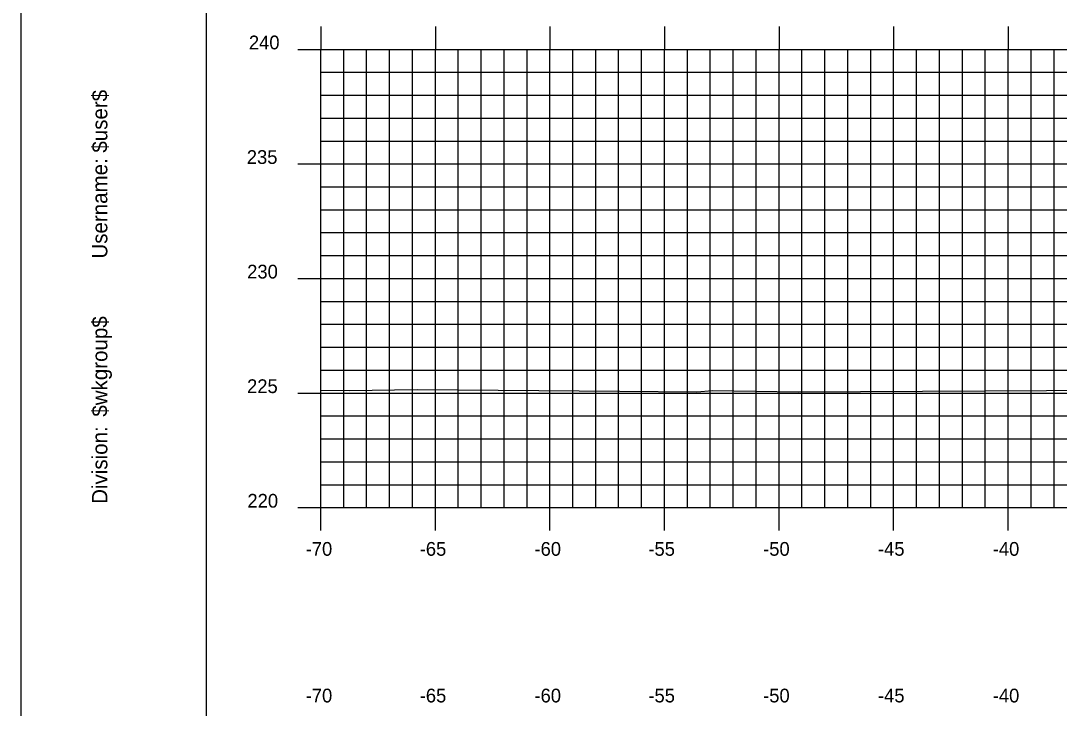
# Model space of a CAD drawing. Extents: x 1136989 to 1137159, y 608981 to 609091.
# Drawn here: x 1136989.05 to 1137034.37, y 609016.58 to 609046.58 of the extents above; entities that cross this region are included whole.
import ezdxf

# ---------------------------------------------------------------- set-up
doc = ezdxf.new("R2010")
doc.units = 0
for name, color, linetype in [('BORDER', 7, 'Continuous'), ('H_V ANNOTATION', 7, 'Continuous'), ('MAJOR', 7, 'Continuous'), ('MINOR', 7, 'Continuous'), ('PLOT BOUNDARY', 7, 'Continuous'), ('S_Roadway_Centerline', 7, 'Continuous')]:
    doc.layers.add(name, color=color, linetype=linetype)

msp = doc.modelspace()

# ---------------------------------------------------------------- linework, layer by layer
at = {"layer": 'BORDER'}
msp.add_lwpolyline([(1136997.14, 608984.335), (1137157.14, 608984.335), (1137157.14, 609089.335), (1136997.14, 609089.335)], close=True, dxfattribs=at)
at = {"layer": 'MAJOR'}
for p, q in [((1137002.14, 609046.337), (1137002.14, 609045.335)), ((1137007.14, 609046.337), (1137007.14, 609045.335)), ((1137012.14, 609046.337), (1137012.14, 609045.335)), ((1137017.14, 609046.337), (1137017.14, 609045.335)), ((1137022.14, 609046.337), (1137022.14, 609045.335)), ((1137027.14, 609046.337), (1137027.14, 609045.335)), ((1137032.14, 609046.337), (1137032.14, 609045.335)), ((1137001.138, 609045.335), (1137002.14, 609045.335)), ((1137002.14, 609045.335), (1137142.14, 609045.335)), ((1137002.14, 609025.335), (1137002.14, 609045.335)), ((1137002.14, 609025.335), (1137002.14, 609045.335)), ((1137002.14, 609045.335), (1137142.14, 609045.335)), ((1137007.14, 609025.335), (1137007.14, 609045.335)), ((1137012.14, 609025.335), (1137012.14, 609045.335)), ((1137017.14, 609025.335), (1137017.14, 609045.335)), ((1137022.14, 609025.335), (1137022.14, 609045.335)), ((1137027.14, 609025.335), (1137027.14, 609045.335)), ((1137032.14, 609025.335), (1137032.14, 609045.335)), ((1137001.138, 609040.335), (1137002.14, 609040.335)), ((1137002.14, 609040.335), (1137142.14, 609040.335)), ((1137001.138, 609035.335), (1137002.14, 609035.335)), ((1137002.14, 609035.335), (1137142.14, 609035.335)), ((1137001.138, 609030.335), (1137002.14, 609030.335)), ((1137002.14, 609030.335), (1137142.14, 609030.335)), ((1137001.138, 609025.335), (1137002.14, 609025.335)), ((1137002.14, 609025.335), (1137142.14, 609025.335)), ((1137002.14, 609025.335), (1137142.14, 609025.335)), ((1137002.14, 609024.333), (1137002.14, 609025.335)), ((1137007.14, 609024.333), (1137007.14, 609025.335)), ((1137012.14, 609024.333), (1137012.14, 609025.335)), ((1137017.14, 609024.333), (1137017.14, 609025.335)), ((1137022.14, 609024.333), (1137022.14, 609025.335)), ((1137027.14, 609024.333), (1137027.14, 609025.335)), ((1137032.14, 609024.333), (1137032.14, 609025.335))]:
    msp.add_line(p, q, dxfattribs=at)
at = {"layer": 'MINOR'}
for p, q in [((1137003.14, 609025.335), (1137003.14, 609045.335)), ((1137004.14, 609025.335), (1137004.14, 609045.335)), ((1137005.14, 609025.335), (1137005.14, 609045.335)), ((1137006.14, 609025.335), (1137006.14, 609045.335)), ((1137008.14, 609025.335), (1137008.14, 609045.335)), ((1137009.14, 609025.335), (1137009.14, 609045.335)), ((1137010.14, 609025.335), (1137010.14, 609045.335)), ((1137011.14, 609025.335), (1137011.14, 609045.335)), ((1137013.14, 609025.335), (1137013.14, 609045.335)), ((1137014.14, 609025.335), (1137014.14, 609045.335)), ((1137015.14, 609025.335), (1137015.14, 609045.335)), ((1137016.14, 609025.335), (1137016.14, 609045.335)), ((1137018.14, 609025.335), (1137018.14, 609045.335)), ((1137019.14, 609025.335), (1137019.14, 609045.335)), ((1137020.14, 609025.335), (1137020.14, 609045.335)), ((1137021.14, 609025.335), (1137021.14, 609045.335)), ((1137023.14, 609025.335), (1137023.14, 609045.335)), ((1137024.14, 609025.335), (1137024.14, 609045.335)), ((1137025.14, 609025.335), (1137025.14, 609045.335)), ((1137026.14, 609025.335), (1137026.14, 609045.335)), ((1137028.14, 609025.335), (1137028.14, 609045.335)), ((1137029.14, 609025.335), (1137029.14, 609045.335)), ((1137030.14, 609025.335), (1137030.14, 609045.335)), ((1137031.14, 609025.335), (1137031.14, 609045.335)), ((1137033.14, 609025.335), (1137033.14, 609045.335)), ((1137034.14, 609025.335), (1137034.14, 609045.335)), ((1137002.14, 609044.335), (1137142.14, 609044.335)), ((1137002.14, 609044.335), (1137003.142, 609044.335)), ((1137002.14, 609043.335), (1137142.14, 609043.335)), ((1137002.14, 609043.335), (1137003.142, 609043.335)), ((1137002.14, 609042.335), (1137142.14, 609042.335)), ((1137002.14, 609042.335), (1137003.142, 609042.335)), ((1137002.14, 609041.335), (1137142.14, 609041.335)), ((1137002.14, 609041.335), (1137003.142, 609041.335)), ((1137002.14, 609039.335), (1137142.14, 609039.335)), ((1137002.14, 609039.335), (1137003.142, 609039.335)), ((1137002.14, 609038.335), (1137142.14, 609038.335)), ((1137002.14, 609038.335), (1137003.142, 609038.335)), ((1137002.14, 609037.335), (1137142.14, 609037.335)), ((1137002.14, 609037.335), (1137003.142, 609037.335)), ((1137002.14, 609036.335), (1137142.14, 609036.335)), ((1137002.14, 609036.335), (1137003.142, 609036.335)), ((1137002.14, 609034.335), (1137142.14, 609034.335)), ((1137002.14, 609034.335), (1137003.142, 609034.335)), ((1137002.14, 609033.335), (1137142.14, 609033.335)), ((1137002.14, 609033.335), (1137003.142, 609033.335)), ((1137002.14, 609032.335), (1137142.14, 609032.335)), ((1137002.14, 609032.335), (1137003.142, 609032.335)), ((1137002.14, 609031.335), (1137142.14, 609031.335)), ((1137002.14, 609031.335), (1137003.142, 609031.335)), ((1137002.14, 609029.335), (1137142.14, 609029.335)), ((1137002.14, 609029.335), (1137003.142, 609029.335)), ((1137002.14, 609028.335), (1137142.14, 609028.335)), ((1137002.14, 609028.335), (1137003.142, 609028.335)), ((1137002.14, 609027.335), (1137142.14, 609027.335)), ((1137002.14, 609027.335), (1137003.142, 609027.335)), ((1137002.14, 609026.335), (1137142.14, 609026.335)), ((1137002.14, 609026.335), (1137003.142, 609026.335))]:
    msp.add_line(p, q, dxfattribs=at)
at = {"layer": 'PLOT BOUNDARY'}
msp.add_lwpolyline([(1136989.047, 608981.276), (1137159.047, 608981.276), (1137159.047, 609091.276), (1136989.047, 609091.276)], close=True, dxfattribs=at)
at = {"layer": 'S_Roadway_Centerline'}
msp.add_lwpolyline([(1137002.14, 609030.462), (1137003.399, 609030.449), (1137006.342, 609030.492), (1137015.185, 609030.419), (1137018.549, 609030.394), (1137019.238, 609030.446), (1137022.99, 609030.389), (1137036.519, 609030.456), (1137040.174, 609030.448), (1137046.657, 609030.914), (1137055.778, 609031.631), (1137061.718, 609034.034), (1137062.247, 609034.265), (1137063.541, 609034.695), (1137073.261, 609035.448), (1137074.968, 609035.579), (1137078.218, 609035.668), (1137085.691, 609035.878), (1137089.945, 609035.87)], dxfattribs=at)

# ---------------------------------------------------------------- texts
at = {"layer": 'BORDER'}
for s, p in [('$user$', (1136992.825, 609040.827)), ('Username:', (1136992.825, 609036.203)), ('$wkgroup$', (1136992.825, 609029.305)), ('Division:', (1136992.825, 609025.501))]:
    msp.add_text(s, height=0.6696, rotation=90, dxfattribs=at).set_placement(p)
at = {"layer": 'H_V ANNOTATION'}
for s, p in [('240', (1136999.002, 609045.335)), ('235', (1136998.911, 609040.335)), ('230', (1136998.927, 609035.335)), ('225', (1136998.922, 609030.335)), ('220', (1136998.938, 609025.335)), ('-70', (1137001.481, 609023.235)), ('-65', (1137006.457, 609023.235)), ('-60', (1137011.465, 609023.235)), ('-55', (1137016.436, 609023.235)), ('-50', (1137021.444, 609023.235)), ('-45', (1137026.457, 609023.235)), ('-40', (1137031.465, 609023.235)), ('-70', (1137001.481, 609016.835)), ('-65', (1137006.457, 609016.835)), ('-60', (1137011.465, 609016.835)), ('-55', (1137016.436, 609016.835)), ('-50', (1137021.444, 609016.835)), ('-45', (1137026.457, 609016.835)), ('-40', (1137031.465, 609016.835))]:
    msp.add_text(s, height=0.6, dxfattribs=at).set_placement(p)
at = {"layer": 'MAJOR'}
msp.add_text('-', height=0.006, dxfattribs=at).set_placement((1137002.135, 609025.335))

doc.saveas('drawing.dxf')
